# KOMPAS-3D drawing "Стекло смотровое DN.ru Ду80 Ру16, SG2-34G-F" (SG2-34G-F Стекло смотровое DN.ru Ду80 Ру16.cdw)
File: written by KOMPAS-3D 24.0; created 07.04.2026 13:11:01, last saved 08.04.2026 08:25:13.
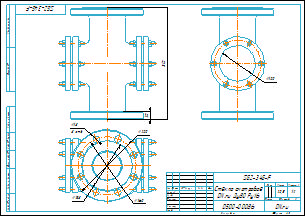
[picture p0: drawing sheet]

Document properties: Автор: Main; Форматы листов документа: A3; Полное имя файла: SG2-34G-F Стекло смотровое DN.ru Ду80 Ру16.m3d; Масса: 20.5; Наименование: Стекло смотровое DN.ru Ду80 Ру16; Количество листов документа: 1; Примечание: D500-00086

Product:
- Part/product: Стекло смотровое DN.ru Ду80 Ру16  | designation SG2-34G-F
    Масса: 20.5
    Раздел спецификации: Прочие изделия
    Примечание: D500-00086

Views: Вид 1, Снизу, Проекционный вид 2, Проекционный вид 3
Referenced files in D:\DN.ru Аутсерс\Стекло смотровое DN.ru\Стекло смотровое DN.ru SG2-34G-F тип В ГОСТ 21836-2021 Ду100 Ру16, углеродистая сталь, фланцевое\: SG2-34G-F тип В Стекло смотровое DN.ru Ду100 Ру16.m3d, SG2-34G-F тип ВСтекло смотровое DN.ru Ду100 Ру16.cdw
Referenced files in D:\DN.ru Аутсерс\Стекло смотровое DN.ru\SG2-34G-F Стекло смотровое DN.ru Ду80 Ру16\: SG2-34G-F Стекло смотровое DN.ru Ду80 Ру16.m3d
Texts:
  SG2-34G-F
  Стекло смотровое
  DN.ru Ду80 Ру16
  Стекло смотровое DN.ru Ду80 Ру16
  SG2-34G-F Стекло смотровое DN.ru Ду80 Ру16
Dimensions and other numbers on the sheet: 0; 3; 2; 4; 310; 20; 200; 138; 18; 8 отв.; 160; 100; 1:2; 1; 20,5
